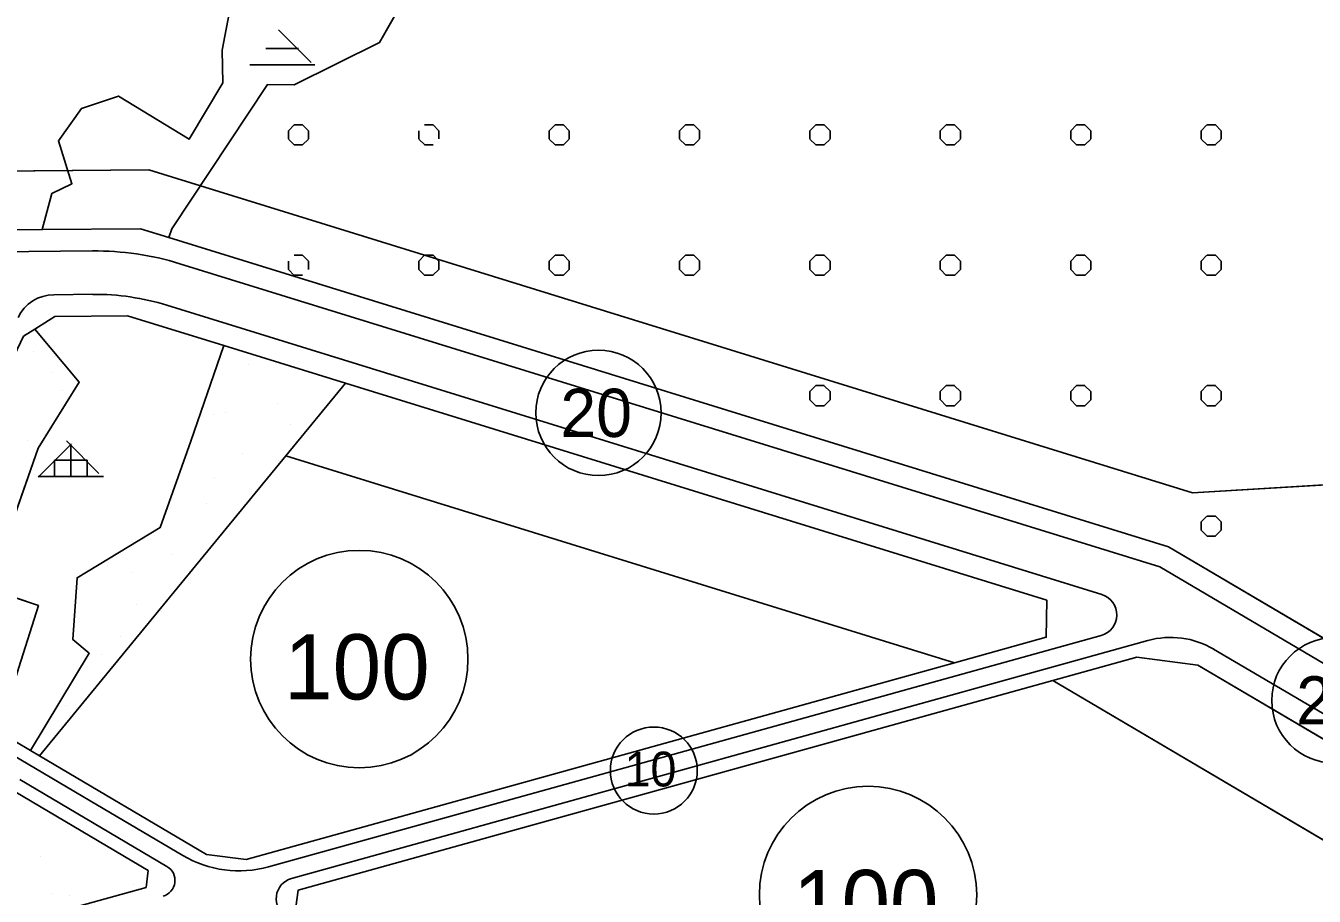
# Model space of a CAD drawing. Extents: x 427903 to 430077, y 4477233 to 4480385.
# Drawn here: x 428100.1 to 428396.6, y 4479090.6 to 4479290.8 of the extents above; entities that cross this region are included whole.
import ezdxf

# ---------------------------------------------------------------- set-up
doc = ezdxf.new("R2010")
doc.units = 0
for name, color, linetype in [('ADA', 7, 'Continuous'), ('ADAKENARI', 7, 'Continuous'), ('KALDIRIM2', 7, 'Continuous'), ('PL_AYA_ORMAN', 7, 'Continuous'), ('PL_AYA_PARK_DINLENME', 7, 'Continuous'), ('PL_KA_TARIM_OZEL', 7, 'Continuous'), ('PL_KON_ONE_100', 7, 'Continuous'), ('PL_ORMAN', 7, 'Continuous'), ('PL_TICARET', 7, 'Continuous'), ('rezerv yapı alan', 7, 'Continuous'), ('SM_DAIRE', 7, 'Continuous'), ('SM_TAKS', 7, 'Continuous'), ('SM_YGEN', 7, 'Continuous'), ('TR_AZYOGUNKONUT', 7, 'Continuous'), ('TR_ORMAN', 7, 'Continuous'), ('TR_OZELMAHSUL', 7, 'Continuous'), ('TR_PARKALANI', 7, 'Continuous'), ('TR_TALIISMERK', 7, 'Continuous')]:
    doc.layers.add(name, color=color, linetype=linetype)

msp = doc.modelspace()

# ---------------------------------------------------------------- linework, layer by layer
at = {"layer": 'ADA'}
for p, q in [((428203.74, 4479325.99), (428181.54, 4479286.96)), ((428145.35, 4479285.19), (428147.24, 4479295.2)), ((428145.45, 4479277.66), (428145.35, 4479285.19)), ((428181.54, 4479286.96), (428161.9, 4479277.22)), ((428155.71, 4479277.28), (428133.74, 4479244.08)), ((428137.74, 4479264.72), (428145.45, 4479277.66)), ((428161.9, 4479277.22), (428155.71, 4479277.28)), ((428112.94, 4479271.75), (428121.44, 4479274.61)), ((428121.44, 4479274.61), (428137.74, 4479264.72)), ((428107.65, 4479264.36), (428112.94, 4479271.75)), ((428110.74, 4479254.47), (428107.65, 4479264.36)), ((428106.16, 4479252.22), (428110.74, 4479254.47)), ((428103.91, 4479243.91), (428106.16, 4479252.22)), ((428133.74, 4479244.08), (428133.03, 4479242.09))]:
    msp.add_line(p, q, dxfattribs=at)
at = {"layer": 'ADAKENARI'}
for p, q in [((427985.63, 4479242.88), (428103.91, 4479243.91)), ((428103.91, 4479243.91), (428126.49, 4479244.11)), ((428126.49, 4479244.11), (428133.03, 4479242.09)), ((428133.03, 4479242.09), (428363.07, 4479170.92)), ((428102.22, 4479221.03), (428106.78, 4479223.94)), ((428106.78, 4479223.94), (428123.55, 4479224.08)), ((428123.55, 4479224.08), (428145.7, 4479217.23)), ((428099.63, 4479219.38), (428102.22, 4479221.03)), ((428102.22, 4479221.03), (428112.43, 4479208.78)), ((428138.08, 4479195.26), (428145.7, 4479217.23)), ((428145.7, 4479217.23), (428173.67, 4479208.58)), ((428112.43, 4479208.78), (428102.97, 4479193.65)), ((428159.95, 4479191.89), (428173.67, 4479208.58)), ((428159.95, 4479191.89), (428173.67, 4479208.58)), ((428159.95, 4479191.89), (428173.67, 4479208.58)), ((428173.67, 4479208.58), (428335.02, 4479158.66)), ((428102.97, 4479193.65), (428091.62, 4479161.26)), ((428131.04, 4479175.35), (428138.08, 4479195.26)), ((428103.25, 4479122.89), (428159.95, 4479191.89)), ((428103.25, 4479122.89), (428159.95, 4479191.89)), ((428103.25, 4479122.89), (428159.95, 4479191.89)), ((428159.95, 4479191.89), (428313.81, 4479144.28)), ((428111.93, 4479163.81), (428131.04, 4479175.35)), ((428363.07, 4479170.92), (428442.85, 4479123.88)), ((428110.99, 4479149.61), (428111.93, 4479163.81)), ((428091.62, 4479161.26), (428103.03, 4479157.43)), ((428335.02, 4479158.66), (428334.9, 4479150.14)), ((428103.03, 4479157.43), (428098.56, 4479143.18)), ((428114.74, 4479146.45), (428110.99, 4479149.61)), ((428313.81, 4479144.28), (428334.9, 4479150.14)), ((428101.23, 4479124.08), (428114.74, 4479146.45)), ((428150.81, 4479098.99), (428313.81, 4479144.28)), ((428336.42, 4479140.19), (428355.79, 4479145.57)), ((428355.79, 4479145.57), (428369.81, 4479143.72)), ((428369.81, 4479143.72), (428427.34, 4479109.8)), ((428162.77, 4479091.94), (428336.42, 4479140.19)), ((428336.42, 4479140.19), (428414.97, 4479093.88)), ((428093.92, 4479128.39), (428101.23, 4479124.08)), ((428101.23, 4479124.08), (428103.25, 4479122.89)), ((428103.25, 4479122.89), (428141.69, 4479100.2)), ((428103.25, 4479122.89), (428141.69, 4479100.2)), ((428103.25, 4479122.89), (428141.69, 4479100.2)), ((428095.74, 4479115.71), (428128.31, 4479096.48)), ((428150.81, 4479098.99), (428141.69, 4479100.2)), ((428150.81, 4479098.99), (428141.69, 4479100.2)), ((428150.81, 4479098.99), (428141.69, 4479100.2)), ((428128.31, 4479096.48), (428127.8, 4479092.6)), ((428104.84, 4479086.22), (428127.8, 4479092.6)), ((428162.26, 4479088.05), (428162.77, 4479091.94))]:
    msp.add_line(p, q, dxfattribs=at)
at = {"layer": 'KALDIRIM2'}
for p, q in [((427993.52, 4479237.95), (428115.48, 4479239.01)), ((428135.57, 4479236.07), (428361.03, 4479166.31)), ((428106.58, 4479228.94), (428115.56, 4479229.02)), ((428132.61, 4479226.51), (428347.68, 4479159.97)), ((428361.03, 4479166.31), (428437.18, 4479121.41)), ((428156, 4479097.32), (428347.55, 4479150.54)), ((428161.27, 4479094.63), (428358.31, 4479149.38)), ((428373.43, 4479147.39), (428434.19, 4479111.57)), ((428095.24, 4479124.13), (428114.96, 4479112.49)), ((428098.73, 4479117.43), (428132.61, 4479097.43)), ((428114.96, 4479112.49), (428136.24, 4479099.93))]:
    msp.add_line(p, q, dxfattribs=at)
for centre, radius, start, end in [((428116.05, 4479172.98), 66.03, 72.8085, 90.4997), ((428106.66, 4479219.75), 9.19, 90.4997, 154.5014), ((428116.05, 4479172.98), 56.03, 72.8085, 90.4997), ((428346.23, 4479155.28), 4.91, 285.5289, 72.8085), ((428363.53, 4479130.6), 19.5, 59.4784, 105.5289), ((428149.19, 4479121.86), 25.46, 239.4461, 285.5289), ((428130.7, 4479094.19), 3.76, 285.5289, 59.4461), ((428162.56, 4479089.99), 4.82, 105.5289, 239.4461)]:
    msp.add_arc(centre, radius, start, end, dxfattribs=at)
at = {"layer": 'PL_AYA_ORMAN'}
msp.add_lwpolyline([(428147.24, 4479295.2), (428145.35, 4479285.19), (428145.45, 4479277.66), (428137.74, 4479264.72), (428121.44, 4479274.61), (428112.94, 4479271.75), (428107.65, 4479264.36), (428110.74, 4479254.47), (428106.16, 4479252.22), (428103.91, 4479243.91), (428126.49, 4479244.11), (428133.03, 4479242.09), (428133.74, 4479244.08), (428155.71, 4479277.28), (428161.9, 4479277.22), (428181.54, 4479286.96), (428203.74, 4479325.99)], dxfattribs=at)
at = {"layer": 'PL_AYA_PARK_DINLENME'}
for points in [[(428091.62, 4479161.26), (428102.97, 4479193.65), (428112.43, 4479208.78), (428102.22, 4479221.03), (428099.63, 4479219.38), (428066.67, 4479150.27), (428068.82, 4479143.21), (428093.92, 4479128.39), (428098.56, 4479143.18), (428103.03, 4479157.43), (428091.62, 4479161.26)], [(428131.04, 4479175.35), (428111.93, 4479163.81), (428110.99, 4479149.61), (428114.74, 4479146.45), (428101.23, 4479124.08), (428103.25, 4479122.89), (428159.95, 4479191.89), (428173.67, 4479208.58), (428145.7, 4479217.23), (428138.08, 4479195.26), (428131.04, 4479175.35)], [(428104.84, 4479086.22), (428127.8, 4479092.6), (428128.31, 4479096.48), (428095.74, 4479115.71), (428081.11, 4479094.29)]]:
    msp.add_lwpolyline(points, dxfattribs=at)
at = {"layer": 'PL_KA_TARIM_OZEL'}
for points in [[(428203.74, 4479325.99), (428181.54, 4479286.96), (428161.9, 4479277.22), (428155.71, 4479277.28), (428133.74, 4479244.08), (428133.03, 4479242.09), (428363.07, 4479170.92), (428442.85, 4479123.88), (428451.51, 4479123.8), (428502.83, 4479152.9)], [(427921.83, 4479274.9), (427966.19, 4479248.19), (427985.63, 4479242.88), (428103.91, 4479243.91), (428106.16, 4479252.22), (428110.74, 4479254.47), (428107.65, 4479264.36), (428112.94, 4479271.75), (428121.44, 4479274.61), (428137.74, 4479264.72), (428145.45, 4479277.66), (428145.35, 4479285.19), (428147.24, 4479295.2)]]:
    msp.add_lwpolyline(points, dxfattribs=at)
at = {"layer": 'PL_KON_ONE_100'}
for points in [[(428313.81, 4479144.28), (428159.95, 4479191.89), (428103.25, 4479122.89), (428141.69, 4479100.2), (428150.81, 4479098.99), (428313.81, 4479144.28)], [(428245.6, 4479042.9), (428334.22, 4479064.44), (428407.87, 4479089.86), (428414.97, 4479093.88), (428336.42, 4479140.19), (428162.77, 4479091.94), (428162.26, 4479088.05), (428236.43, 4479044.27), (428245.6, 4479042.9)]]:
    msp.add_lwpolyline(points, dxfattribs=at)
at = {"layer": 'PL_ORMAN'}
msp.add_lwpolyline([(428103.03, 4479157.43), (428098.56, 4479143.18), (428093.92, 4479128.39), (428101.23, 4479124.08), (428114.74, 4479146.45), (428110.99, 4479149.61), (428111.93, 4479163.81), (428131.04, 4479175.35), (428138.08, 4479195.26), (428145.7, 4479217.23), (428123.55, 4479224.08), (428106.78, 4479223.94), (428102.22, 4479221.03), (428112.43, 4479208.78), (428102.97, 4479193.65), (428091.62, 4479161.26), (428103.03, 4479157.43)], dxfattribs=at)
at = {"layer": 'PL_TICARET'}
for points in [[(428159.95, 4479191.89), (428313.81, 4479144.28), (428334.9, 4479150.14), (428335.02, 4479158.66), (428173.67, 4479208.58), (428159.95, 4479191.89)], [(428336.42, 4479140.19), (428414.97, 4479093.88), (428427.27, 4479100.86), (428427.34, 4479109.8), (428369.81, 4479143.72), (428355.79, 4479145.57), (428336.42, 4479140.19)]]:
    msp.add_lwpolyline(points, dxfattribs=at)
at = {"layer": 'rezerv yapı alan'}
for p, q in [((427987.38, 4479256.4), (428128.47, 4479257.63)), ((428128.47, 4479257.63), (428368.56, 4479183.35)), ((428368.56, 4479183.35), (428552.54, 4479194.57))]:
    msp.add_line(p, q, dxfattribs=at)
msp.add_lwpolyline([(427921.98, 4479290.57), (427971.55, 4479260.72), (427987.38, 4479256.4), (428128.47, 4479257.63), (428368.56, 4479183.35), (428552.54, 4479194.57), (428656.99, 4479201.54), (428694.28, 4479196.96), (428778.69, 4479177.41), (428853.9, 4479147.32), (428942.46, 4479108.55), (429057.71, 4479108.55), (429083.4, 4479100.66), (429102.93, 4479079.75), (429129.55, 4479022.57), (429151, 4479001.12), (429217.97, 4478963.3), (429343.9, 4478891.1), (429611.87, 4478938.66), (429782.06, 4478938.49), (429965.11, 4478882.46), (430027.68, 4478900.91), (430040.04, 4478910.67)], dxfattribs=at)
at = {"layer": 'SM_DAIRE'}
for centre, radius in [((428231.89, 4479201.75), 14.42), ((428176.85, 4479145.11), 25), ((428401.21, 4479135.62), 14.42), ((428244.62, 4479119.48), 10), ((428293.92, 4479090.87), 25)]:
    msp.add_circle(centre, radius, dxfattribs=at)
at = {"layer": 'TR_AZYOGUNKONUT'}
for points in [[(428150.81, 4479098.99), (428313.81, 4479144.28), (428159.95, 4479191.89), (428103.25, 4479122.89), (428141.69, 4479100.2), (428150.81, 4479098.99)], [(428162.26, 4479088.05), (428236.43, 4479044.27), (428245.6, 4479042.9), (428334.22, 4479064.44), (428407.87, 4479089.86), (428414.97, 4479093.88), (428336.42, 4479140.19), (428162.77, 4479091.94), (428162.26, 4479088.05)]]:
    msp.add_lwpolyline(points, dxfattribs=at)
for centre, start, end in [((428176.85, 4479145.11), 0, 180), ((428176.85, 4479145.11), 180, 0), ((428293.92, 4479090.87), 0, 180), ((428293.92, 4479090.87), 180, 0)]:
    msp.add_arc(centre, 25, start, end, dxfattribs=at)
at = {"layer": 'TR_ORMAN'}
for p, q in [((428165.78, 4479282.37), (428158.28, 4479289.87)), ((428155.39, 4479285.56), (428162.89, 4479285.56)), ((428151.64, 4479281.81), (428166.64, 4479281.81)), ((428103, 4479186.99), (428110.49, 4479194.49)), ((428116.97, 4479187.81), (428109.47, 4479195.31)), ((428110.5, 4479187.11), (428110.5, 4479194.61)), ((428106.75, 4479190.86), (428114.25, 4479190.86)), ((428106.75, 4479187.11), (428106.75, 4479190.86)), ((428114.25, 4479187.11), (428114.25, 4479190.86)), ((428103, 4479187.11), (428118, 4479187.11))]:
    msp.add_line(p, q, dxfattribs=at)
at = {"layer": 'TR_OZELMAHSUL'}
for p, q in [((428160.54, 4479266.66), (428161.9, 4479268.01)), ((428161.9, 4479268.02), (428163.82, 4479268.02)), ((428165.18, 4479266.65), (428163.83, 4479268)), ((428191.9, 4479268.02), (428193.82, 4479268.02)), ((428195.18, 4479266.65), (428193.83, 4479268)), ((428220.54, 4479266.66), (428221.9, 4479268.01)), ((428221.9, 4479268.02), (428223.82, 4479268.02)), ((428225.18, 4479266.65), (428223.82, 4479268)), ((428250.54, 4479266.66), (428251.9, 4479268.01)), ((428251.9, 4479268.02), (428253.82, 4479268.02)), ((428255.18, 4479266.65), (428253.82, 4479268)), ((428280.54, 4479266.65), (428281.89, 4479268.01)), ((428281.9, 4479268.02), (428283.82, 4479268.02)), ((428285.18, 4479266.65), (428283.82, 4479268)), ((428310.54, 4479266.65), (428311.89, 4479268.01)), ((428311.9, 4479268.02), (428313.82, 4479268.02)), ((428315.18, 4479266.65), (428313.82, 4479268)), ((428340.54, 4479266.65), (428341.89, 4479268.01)), ((428341.9, 4479268.02), (428343.82, 4479268.02)), ((428345.18, 4479266.65), (428343.82, 4479268)), ((428370.54, 4479266.65), (428371.89, 4479268.01)), ((428371.9, 4479268.02), (428373.82, 4479268.02)), ((428375.18, 4479266.65), (428373.82, 4479268)), ((428160.54, 4479264.75), (428160.54, 4479266.66)), ((428161.91, 4479263.38), (428160.56, 4479264.73)), ((428163.81, 4479263.39), (428165.17, 4479264.74)), ((428165.17, 4479264.75), (428165.17, 4479266.66)), ((428190.54, 4479264.75), (428190.54, 4479266.66)), ((428191.91, 4479263.38), (428190.56, 4479264.73)), ((428195.17, 4479264.75), (428195.17, 4479266.66)), ((428220.54, 4479264.75), (428220.54, 4479266.66)), ((428221.91, 4479263.38), (428220.55, 4479264.73)), ((428223.81, 4479263.39), (428225.17, 4479264.74)), ((428225.17, 4479264.75), (428225.17, 4479266.66)), ((428250.54, 4479264.75), (428250.54, 4479266.66)), ((428251.91, 4479263.38), (428250.55, 4479264.73)), ((428253.81, 4479263.39), (428255.17, 4479264.74)), ((428255.17, 4479264.75), (428255.17, 4479266.66)), ((428280.54, 4479264.75), (428280.54, 4479266.66)), ((428281.91, 4479263.38), (428280.55, 4479264.73)), ((428283.81, 4479263.38), (428285.16, 4479264.74)), ((428285.17, 4479264.75), (428285.17, 4479266.66)), ((428310.54, 4479264.75), (428310.54, 4479266.66)), ((428311.91, 4479263.38), (428310.55, 4479264.73)), ((428313.81, 4479263.38), (428315.16, 4479264.74)), ((428315.17, 4479264.75), (428315.17, 4479266.66)), ((428340.54, 4479264.75), (428340.54, 4479266.66)), ((428341.91, 4479263.38), (428340.55, 4479264.73)), ((428343.81, 4479263.38), (428345.16, 4479264.74)), ((428345.17, 4479264.75), (428345.17, 4479266.66)), ((428370.54, 4479264.75), (428370.54, 4479266.66)), ((428371.91, 4479263.38), (428370.55, 4479264.73)), ((428373.81, 4479263.38), (428375.16, 4479264.74)), ((428375.17, 4479264.75), (428375.17, 4479266.66)), ((428161.9, 4479263.39), (428163.82, 4479263.39)), ((428191.9, 4479263.39), (428193.82, 4479263.39)), ((428221.9, 4479263.39), (428223.82, 4479263.39)), ((428251.9, 4479263.39), (428253.82, 4479263.39)), ((428281.9, 4479263.39), (428283.82, 4479263.39)), ((428311.9, 4479263.39), (428313.82, 4479263.39)), ((428341.9, 4479263.39), (428343.82, 4479263.39)), ((428371.9, 4479263.39), (428373.82, 4479263.39)), ((428161.9, 4479238.02), (428163.82, 4479238.02)), ((428165.18, 4479236.65), (428163.82, 4479238)), ((428190.54, 4479236.66), (428191.9, 4479238.01)), ((428191.9, 4479238.02), (428193.82, 4479238.02)), ((428195.18, 4479236.65), (428193.82, 4479238)), ((428220.54, 4479236.66), (428221.9, 4479238.01)), ((428221.9, 4479238.02), (428223.82, 4479238.02)), ((428225.18, 4479236.65), (428223.82, 4479238)), ((428250.54, 4479236.66), (428251.9, 4479238.01)), ((428251.9, 4479238.02), (428253.82, 4479238.02)), ((428255.18, 4479236.65), (428253.82, 4479238)), ((428280.54, 4479236.66), (428281.89, 4479238.01)), ((428281.9, 4479238.02), (428283.82, 4479238.02)), ((428285.18, 4479236.65), (428283.82, 4479238)), ((428310.54, 4479236.65), (428311.89, 4479238.01)), ((428311.9, 4479238.02), (428313.82, 4479238.02)), ((428315.18, 4479236.65), (428313.82, 4479238)), ((428340.54, 4479236.65), (428341.89, 4479238.01)), ((428341.9, 4479238.02), (428343.82, 4479238.02)), ((428345.18, 4479236.65), (428343.82, 4479238)), ((428370.54, 4479236.65), (428371.89, 4479238.01)), ((428371.9, 4479238.02), (428373.82, 4479238.02)), ((428375.18, 4479236.65), (428373.82, 4479238)), ((428160.54, 4479234.75), (428160.54, 4479236.66)), ((428161.91, 4479233.38), (428160.55, 4479234.73)), ((428165.17, 4479234.75), (428165.17, 4479236.66)), ((428190.54, 4479234.75), (428190.54, 4479236.66)), ((428191.91, 4479233.38), (428190.55, 4479234.73)), ((428193.81, 4479233.39), (428195.17, 4479234.74)), ((428195.17, 4479234.75), (428195.17, 4479236.66)), ((428220.54, 4479234.75), (428220.54, 4479236.66)), ((428221.91, 4479233.38), (428220.55, 4479234.73)), ((428223.81, 4479233.39), (428225.17, 4479234.74)), ((428225.17, 4479234.75), (428225.17, 4479236.66)), ((428250.54, 4479234.75), (428250.54, 4479236.66)), ((428251.91, 4479233.38), (428250.55, 4479234.73)), ((428253.81, 4479233.39), (428255.17, 4479234.74)), ((428255.17, 4479234.75), (428255.17, 4479236.66)), ((428280.54, 4479234.75), (428280.54, 4479236.66)), ((428281.91, 4479233.38), (428280.55, 4479234.73)), ((428283.81, 4479233.39), (428285.16, 4479234.74)), ((428285.17, 4479234.75), (428285.17, 4479236.66)), ((428310.54, 4479234.75), (428310.54, 4479236.66)), ((428311.91, 4479233.38), (428310.55, 4479234.73)), ((428313.81, 4479233.38), (428315.16, 4479234.74)), ((428315.17, 4479234.75), (428315.17, 4479236.66)), ((428340.54, 4479234.75), (428340.54, 4479236.66)), ((428341.91, 4479233.38), (428340.55, 4479234.73)), ((428343.81, 4479233.38), (428345.16, 4479234.74)), ((428345.17, 4479234.75), (428345.17, 4479236.66)), ((428370.54, 4479234.75), (428370.54, 4479236.66)), ((428371.91, 4479233.38), (428370.55, 4479234.73)), ((428373.81, 4479233.38), (428375.16, 4479234.74)), ((428375.17, 4479234.75), (428375.17, 4479236.66)), ((428161.9, 4479233.39), (428163.82, 4479233.39)), ((428191.9, 4479233.39), (428193.82, 4479233.39)), ((428221.9, 4479233.39), (428223.82, 4479233.39)), ((428251.9, 4479233.39), (428253.82, 4479233.39)), ((428281.9, 4479233.39), (428283.82, 4479233.39)), ((428311.9, 4479233.39), (428313.82, 4479233.39)), ((428341.9, 4479233.39), (428343.82, 4479233.39)), ((428371.9, 4479233.39), (428373.82, 4479233.39)), ((428281.9, 4479208.02), (428283.82, 4479208.02)), ((428311.9, 4479208.02), (428313.82, 4479208.02)), ((428341.9, 4479208.02), (428343.82, 4479208.02)), ((428371.9, 4479208.02), (428373.82, 4479208.02)), ((428280.54, 4479206.66), (428281.89, 4479208.01)), ((428280.54, 4479204.75), (428280.54, 4479206.66)), ((428285.18, 4479206.65), (428283.82, 4479208)), ((428285.17, 4479204.75), (428285.17, 4479206.66)), ((428310.54, 4479206.65), (428311.89, 4479208.01)), ((428310.54, 4479204.75), (428310.54, 4479206.66)), ((428315.18, 4479206.65), (428313.82, 4479208)), ((428315.17, 4479204.75), (428315.17, 4479206.66)), ((428340.54, 4479206.65), (428341.89, 4479208.01)), ((428340.54, 4479204.75), (428340.54, 4479206.66)), ((428345.18, 4479206.65), (428343.82, 4479208)), ((428345.17, 4479204.75), (428345.17, 4479206.66)), ((428370.54, 4479206.65), (428371.89, 4479208.01)), ((428370.54, 4479204.75), (428370.54, 4479206.66)), ((428375.18, 4479206.65), (428373.82, 4479208)), ((428375.17, 4479204.75), (428375.17, 4479206.66)), ((428281.91, 4479203.38), (428280.55, 4479204.73)), ((428281.9, 4479203.39), (428283.82, 4479203.39)), ((428283.81, 4479203.39), (428285.16, 4479204.74)), ((428311.91, 4479203.38), (428310.55, 4479204.73)), ((428311.9, 4479203.39), (428313.82, 4479203.39)), ((428313.81, 4479203.38), (428315.16, 4479204.74)), ((428341.91, 4479203.38), (428340.55, 4479204.73)), ((428341.9, 4479203.39), (428343.82, 4479203.39)), ((428343.81, 4479203.38), (428345.16, 4479204.74)), ((428371.91, 4479203.38), (428370.55, 4479204.73)), ((428371.9, 4479203.39), (428373.82, 4479203.39)), ((428373.81, 4479203.38), (428375.16, 4479204.74)), ((428370.54, 4479176.65), (428371.89, 4479178.01)), ((428370.54, 4479174.75), (428370.54, 4479176.66)), ((428371.9, 4479178.02), (428373.82, 4479178.02)), ((428375.18, 4479176.65), (428373.82, 4479178.01)), ((428375.17, 4479174.75), (428375.17, 4479176.66)), ((428371.91, 4479173.38), (428370.55, 4479174.74)), ((428371.9, 4479173.39), (428373.82, 4479173.39)), ((428373.81, 4479173.38), (428375.16, 4479174.74))]:
    msp.add_line(p, q, dxfattribs=at)
at = {"layer": 'TR_PARKALANI'}
for p, q in [((428102.01, 4479215.86), (428102.01, 4479215.86)), ((428102.01, 4479215.86), (428102.01, 4479215.86)), ((428152.2, 4479215.08), (428152.2, 4479215.08)), ((428151.35, 4479212.96), (428151.35, 4479212.96)), ((428151.35, 4479212.96), (428151.35, 4479212.96)), ((428106.14, 4479210.94), (428106.14, 4479210.94)), ((428106.14, 4479210.94), (428106.14, 4479210.94)), ((428108.68, 4479206.88), (428108.68, 4479206.88)), ((428108.68, 4479206.88), (428108.68, 4479206.88)), ((428158.01, 4479203.98), (428158.01, 4479203.98)), ((428158.01, 4479203.98), (428158.01, 4479203.98)), ((428143.24, 4479201.37), (428143.24, 4479201.37)), ((428143.24, 4479201.37), (428143.24, 4479201.37)), ((428146.19, 4479201.77), (428146.19, 4479201.77)), ((428160.97, 4479199.16), (428160.97, 4479199.16)), ((428100.56, 4479195.29), (428100.56, 4479195.29)), ((428100.56, 4479195.29), (428100.56, 4479195.29)), ((428149.9, 4479192.39), (428149.9, 4479192.39)), ((428149.9, 4479192.39), (428149.9, 4479192.39)), ((428143.59, 4479186.99), (428143.59, 4479186.99)), ((428141.79, 4479180.81), (428141.79, 4479180.81)), ((428141.79, 4479180.81), (428141.79, 4479180.81)), ((428118.9, 4479166.62), (428118.9, 4479166.62)), ((428118.9, 4479166.62), (428118.9, 4479166.62)), ((428133.68, 4479169.22), (428133.68, 4479169.22)), ((428133.68, 4479169.22), (428133.68, 4479169.22)), ((428124.47, 4479164.98), (428124.47, 4479164.98)), ((428125.56, 4479157.64), (428125.56, 4479157.64)), ((428125.56, 4479157.64), (428125.56, 4479157.64)), ((428111.43, 4479154.76), (428111.43, 4479154.76)), ((428101.21, 4479154.59), (428101.21, 4479154.59)), ((428101.21, 4479154.59), (428101.21, 4479154.59)), ((428121.87, 4479150.21), (428121.87, 4479150.21)), ((428117.45, 4479146.06), (428117.45, 4479146.06)), ((428117.45, 4479146.06), (428117.45, 4479146.06)), ((428109.34, 4479134.47), (428109.34, 4479134.47)), ((428109.34, 4479134.47), (428109.34, 4479134.47)), ((428118.27, 4479102.28), (428118.27, 4479102.28)), ((428118.27, 4479102.28), (428118.27, 4479102.28)), ((428103.5, 4479099.68), (428103.5, 4479099.68)), ((428103.5, 4479099.68), (428103.5, 4479099.68)), ((428124.93, 4479093.3), (428124.93, 4479093.3)), ((428124.93, 4479093.3), (428124.93, 4479093.3)), ((428106.27, 4479091.16), (428106.27, 4479091.16)), ((428110.16, 4479090.7), (428110.16, 4479090.7)), ((428110.16, 4479090.7), (428110.16, 4479090.7))]:
    msp.add_line(p, q, dxfattribs=at)
at = {"layer": 'TR_TALIISMERK'}
for points in [[(428335.02, 4479158.66), (428173.67, 4479208.58), (428159.95, 4479191.89), (428313.81, 4479144.28), (428334.9, 4479150.14), (428335.02, 4479158.66)], [(428355.79, 4479145.57), (428336.42, 4479140.19), (428414.97, 4479093.88), (428427.27, 4479100.86), (428427.34, 4479109.8), (428369.81, 4479143.72), (428355.79, 4479145.57)]]:
    msp.add_lwpolyline(points, dxfattribs=at)

# ---------------------------------------------------------------- texts
at = {"layer": 'SM_TAKS'}
for p in [(428159.58, 4479135.84), (428276.65, 4479081.61)]:
    msp.add_text('100', height=15, dxfattribs=at).set_placement(p)
at = {"layer": 'SM_YGEN'}
for s, height, p in [('20', 11.092, (428223.11, 4479196.21)), ('20', 11.092, (428392.43, 4479130.07)), ('10', 8, (428237.91, 4479115.82))]:
    msp.add_text(s, height=height, rotation=0.0002, dxfattribs=at).set_placement(p)

doc.saveas('drawing.dxf')
